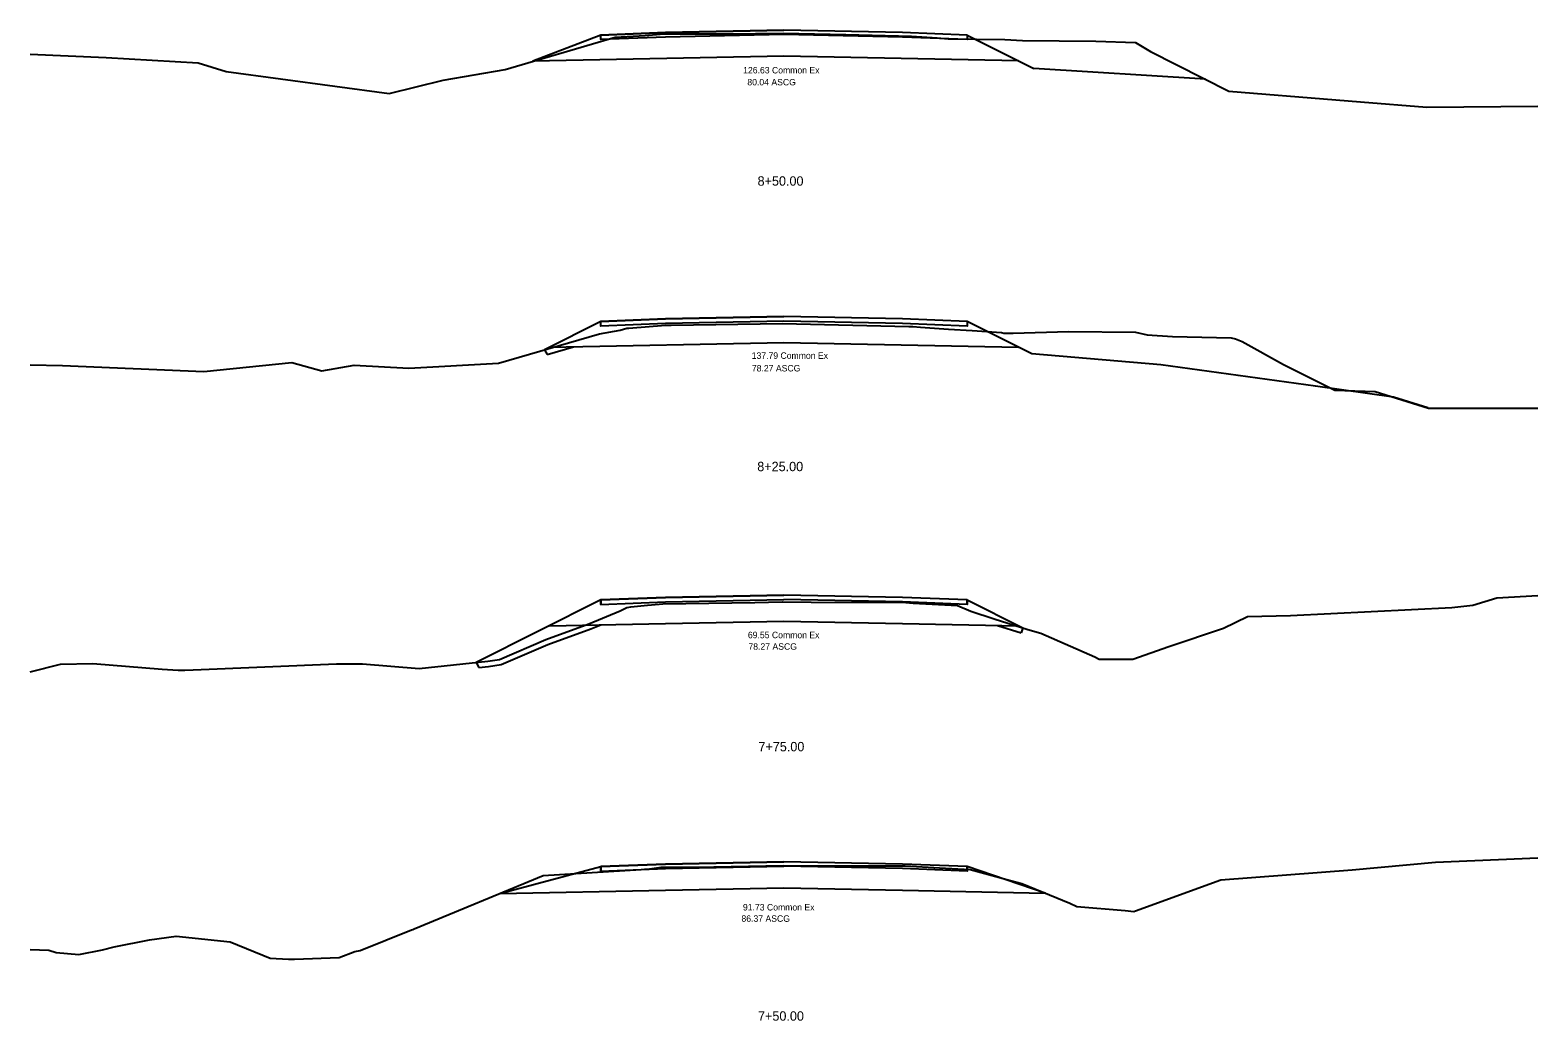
# Model space of a CAD drawing. Extents: x 2194256 to 2194747, y 863888 to 863998.
# Drawn here: x 2194606.7 to 2194746.7, y 863895.1 to 863987 of the extents above; entities that cross this region are included whole.
import ezdxf

# ---------------------------------------------------------------- set-up
doc = ezdxf.new("R2010")
doc.units = 0
for name, color, linetype in [('Approach', 7, 'Continuous'), ('H_V ANNOTATION', 7, 'Continuous'), ('S_Roadway_Centerline', 7, 'Continuous'), ('TEMPLATE', 7, 'Continuous')]:
    doc.layers.add(name, color=color, linetype=linetype)

msp = doc.modelspace()

# ---------------------------------------------------------------- linework, layer by layer
at = {"layer": 'S_Roadway_Centerline'}
for points in [[(2194606.74, 863984.78), (2194613.81, 863984.46), (2194622.33, 863983.98), (2194624.94, 863983.17), (2194640.09, 863981.14), (2194645.1, 863982.35), (2194650.86, 863983.37), (2194661.06, 863986.37), (2194663.86, 863986.52), (2194665.57, 863986.66), (2194671.54, 863986.67), (2194676.68, 863986.74), (2194682.48, 863986.61), (2194688.57, 863986.45), (2194690.96, 863986.28), (2194692, 863986.21), (2194697.24, 863986.13), (2194698.88, 863986.05), (2194705.7, 863985.99), (2194709.37, 863985.87), (2194710.79, 863985.02), (2194718.04, 863981.34), (2194727.98, 863980.53), (2194730.27, 863980.34), (2194736.44, 863979.87), (2194746.74, 863979.94)], [(2194606.74, 863955.95), (2194609.75, 863955.89), (2194622.86, 863955.34), (2194631.05, 863956.17), (2194633.84, 863955.4), (2194636.83, 863955.92), (2194641.92, 863955.64), (2194650.24, 863956.09), (2194659.62, 863958.83), (2194661.53, 863959.17), (2194662.15, 863959.35), (2194662.32, 863959.36), (2194665.73, 863959.64), (2194666.25, 863959.64), (2194676.61, 863959.78), (2194688.32, 863959.51), (2194688.72, 863959.5), (2194689.42, 863959.45), (2194692.03, 863959.24), (2194694.22, 863959.12), (2194696.93, 863958.93), (2194697.15, 863958.88), (2194698.01, 863958.88), (2194703.17, 863959.04), (2194709.39, 863958.99), (2194710.45, 863958.73), (2194712.83, 863958.58), (2194718.27, 863958.45), (2194718.68, 863958.37), (2194719.3, 863958.11), (2194723.13, 863955.96), (2194727.88, 863953.59), (2194731.65, 863953.47), (2194736.6, 863951.93), (2194736.66, 863951.91), (2194736.68, 863951.91), (2194746.74, 863951.93)], [(2194606.74, 863927.46), (2194609.55, 863928.15), (2194612.55, 863928.23), (2194619.01, 863927.71), (2194620.49, 863927.62), (2194621.11, 863927.6), (2194621.89, 863927.64), (2194635.19, 863928.2), (2194637.6, 863928.19), (2194642.86, 863927.76), (2194649.25, 863928.44), (2194650.34, 863928.6), (2194654.62, 863930.46), (2194658.62, 863931.9), (2194661.54, 863933.12), (2194662.16, 863933.42), (2194662.51, 863933.47), (2194664.08, 863933.64), (2194665.14, 863933.72), (2194665.49, 863933.76), (2194674.02, 863933.89), (2194676.57, 863933.94), (2194676.59, 863933.94), (2194679.26, 863933.91), (2194688.05, 863933.87), (2194688.75, 863933.83), (2194692.85, 863933.6), (2194694.1, 863933.09), (2194696.25, 863932.36), (2194699.38, 863931.39), (2194700.58, 863931.05), (2194705.6, 863928.85), (2194706.01, 863928.64), (2194706.16, 863928.63), (2194709.13, 863928.62), (2194712.49, 863929.81), (2194717.56, 863931.5), (2194719.77, 863932.59), (2194723.77, 863932.69), (2194738.75, 863933.43), (2194740.72, 863933.63), (2194742.92, 863934.32), (2194746.74, 863934.54)], [(2194606.74, 863901.68), (2194608.49, 863901.63), (2194609.16, 863901.41), (2194611.27, 863901.21), (2194613.46, 863901.64), (2194614.55, 863901.94), (2194617.83, 863902.58), (2194620.31, 863902.92), (2194625.31, 863902.38), (2194629.03, 863900.89), (2194630.74, 863900.79), (2194631.28, 863900.78), (2194635.43, 863900.94), (2194636.89, 863901.5), (2194637.39, 863901.58), (2194642.14, 863903.49), (2194642.28, 863903.55), (2194642.41, 863903.59), (2194654.39, 863908.55), (2194663.49, 863909.09), (2194663.81, 863909.13), (2194664.05, 863909.15), (2194665.35, 863909.32), (2194670.23, 863909.36), (2194676.65, 863909.46), (2194683.27, 863909.43), (2194687.99, 863909.44), (2194691.17, 863909.26), (2194694.03, 863909.11), (2194697.76, 863908.09), (2194698.82, 863907.8), (2194703.28, 863905.99), (2194703.94, 863905.66), (2194708.42, 863905.3), (2194709.24, 863905.22), (2194709.37, 863905.26), (2194717.3, 863908.15), (2194729.51, 863909.08), (2194737.25, 863909.77), (2194746.74, 863910.18)]]:
    msp.add_lwpolyline(points, dxfattribs=at)
at = {"layer": 'TEMPLATE'}
for p, q in [((2194659.74, 863986.55), (2194653.42, 863984.12)), ((2194665.74, 863986.79), (2194659.74, 863986.55)), ((2194665.74, 863986.79), (2194676.74, 863987.01)), ((2194676.74, 863987.01), (2194665.74, 863986.79)), ((2194676.74, 863986.59), (2194665.74, 863986.37)), ((2194687.74, 863986.79), (2194676.74, 863987.01)), ((2194687.74, 863986.37), (2194676.74, 863986.59)), ((2194693.74, 863986.55), (2194687.74, 863986.79)), ((2194693.74, 863986.55), (2194699.94, 863983.45)), ((2194676.74, 863984.59), (2194653.42, 863984.12)), ((2194698.53, 863984.15), (2194676.74, 863984.59)), ((2194715.87, 863982.45), (2194699.94, 863983.45)), ((2194659.74, 863959.96), (2194654.51, 863957.34)), ((2194665.74, 863960.2), (2194659.74, 863959.96)), ((2194665.74, 863960.2), (2194676.74, 863960.42)), ((2194676.74, 863960.42), (2194665.74, 863960.2)), ((2194676.74, 863960), (2194665.74, 863959.78)), ((2194687.74, 863960.2), (2194676.74, 863960.42)), ((2194687.74, 863959.78), (2194676.74, 863960)), ((2194693.74, 863959.96), (2194687.74, 863960.2)), ((2194654.51, 863957.34), (2194654.74, 863956.89)), ((2194676.74, 863958), (2194654.96, 863957.56)), ((2194698.53, 863957.56), (2194676.74, 863958)), ((2194665.74, 863934.36), (2194676.74, 863934.58)), ((2194676.74, 863934.58), (2194665.74, 863934.36)), ((2194687.74, 863934.36), (2194676.74, 863934.58)), ((2194659.74, 863934.12), (2194648.16, 863928.32)), ((2194665.74, 863934.36), (2194659.74, 863934.12)), ((2194665.74, 863933.94), (2194676.74, 863934.16)), ((2194687.74, 863933.94), (2194676.74, 863934.16)), ((2194693.74, 863934.12), (2194687.74, 863934.36)), ((2194693.74, 863934.12), (2194698.91, 863931.53)), ((2194698.91, 863931.53), (2194698.77, 863931.08)), ((2194648.16, 863928.32), (2194648.4, 863927.85)), ((2194650.36, 863906.88), (2194659.74, 863909.37)), ((2194665.74, 863909.61), (2194659.74, 863909.37)), ((2194665.74, 863909.61), (2194676.74, 863909.83)), ((2194676.74, 863909.83), (2194665.74, 863909.61)), ((2194665.74, 863909.19), (2194676.74, 863909.41)), ((2194687.74, 863909.61), (2194676.74, 863909.83)), ((2194687.74, 863909.19), (2194676.74, 863909.41)), ((2194693.74, 863909.37), (2194687.74, 863909.61)), ((2194700.98, 863906.92), (2194693.74, 863909.37))]:
    msp.add_line(p, q, dxfattribs=at)
for points in [[(2194659.74, 863986.55), (2194659.74, 863986.55), (2194665.74, 863986.79)], [(2194665.74, 863986.37), (2194659.74, 863986.13), (2194659.74, 863986.55)], [(2194693.74, 863986.55), (2194693.74, 863986.13), (2194687.74, 863986.37)], [(2194659.74, 863959.96), (2194659.74, 863959.96), (2194665.74, 863960.2)], [(2194665.74, 863959.78), (2194659.74, 863959.54), (2194659.74, 863959.96)], [(2194693.74, 863959.96), (2194693.74, 863959.54), (2194687.74, 863959.78)], [(2194736.54, 863951.95), (2194733.33, 863952.95), (2194726.11, 863953.95), (2194718.9, 863954.95), (2194711.72, 863955.95), (2194699.76, 863956.95), (2194693.74, 863959.96)], [(2194654.74, 863956.89), (2194657.21, 863957.61)], [(2194659.74, 863934.12), (2194659.74, 863934.12), (2194665.74, 863934.36)], [(2194659.74, 863933.7), (2194659.74, 863934.12), (2194659.74, 863933.7), (2194665.74, 863933.94)], [(2194693.74, 863933.7), (2194693.74, 863934.12), (2194693.74, 863933.7), (2194687.74, 863933.94)], [(2194648.4, 863927.85), (2194649.31, 863927.94), (2194650.48, 863928.12), (2194654.81, 863930), (2194658.8, 863931.44), (2194659.72, 863931.82)], [(2194654.96, 863931.72), (2194665.74, 863931.94), (2194676.74, 863932.16), (2194687.74, 863931.94), (2194698.53, 863931.72)], [(2194696.56, 863931.76), (2194698.77, 863931.08)], [(2194659.74, 863909.37), (2194659.74, 863909.37), (2194665.74, 863909.61)], [(2194659.74, 863908.95), (2194659.74, 863909.37), (2194659.74, 863908.95), (2194665.74, 863909.19)], [(2194693.74, 863908.95), (2194693.74, 863909.37), (2194693.74, 863908.95), (2194687.74, 863909.19)], [(2194650.36, 863906.88), (2194665.74, 863907.19), (2194676.74, 863907.41), (2194687.74, 863907.19), (2194700.98, 863906.92)]]:
    msp.add_lwpolyline(points, dxfattribs=at)

# ---------------------------------------------------------------- texts
at = {"layer": 'Approach'}
for s, p in [('126.63 Common Ex', (2194672.95, 863982.99)), ('80.04 ASCG', (2194673.34, 863981.88)), ('137.79 Common Ex', (2194673.74, 863956.5)), ('78.27 ASCG', (2194673.76, 863955.33)), ('69.55 Common Ex', (2194673.39, 863930.57)), ('78.27 ASCG', (2194673.44, 863929.5)), ('91.73 Common Ex', (2194672.93, 863905.3)), ('86.37 ASCG', (2194672.79, 863904.25))]:
    msp.add_text(s, height=0.6, dxfattribs=at).set_placement(p)
at = {"layer": 'H_V ANNOTATION'}
for s, p in [('8+50.00', (2194674.29, 863972.57)), ('8+25.00', (2194674.26, 863946.07)), ('7+75.00', (2194674.37, 863920.07)), ('7+50.00', (2194674.33, 863895.07))]:
    msp.add_text(s, height=0.875, dxfattribs=at).set_placement(p)

doc.saveas('drawing.dxf')
